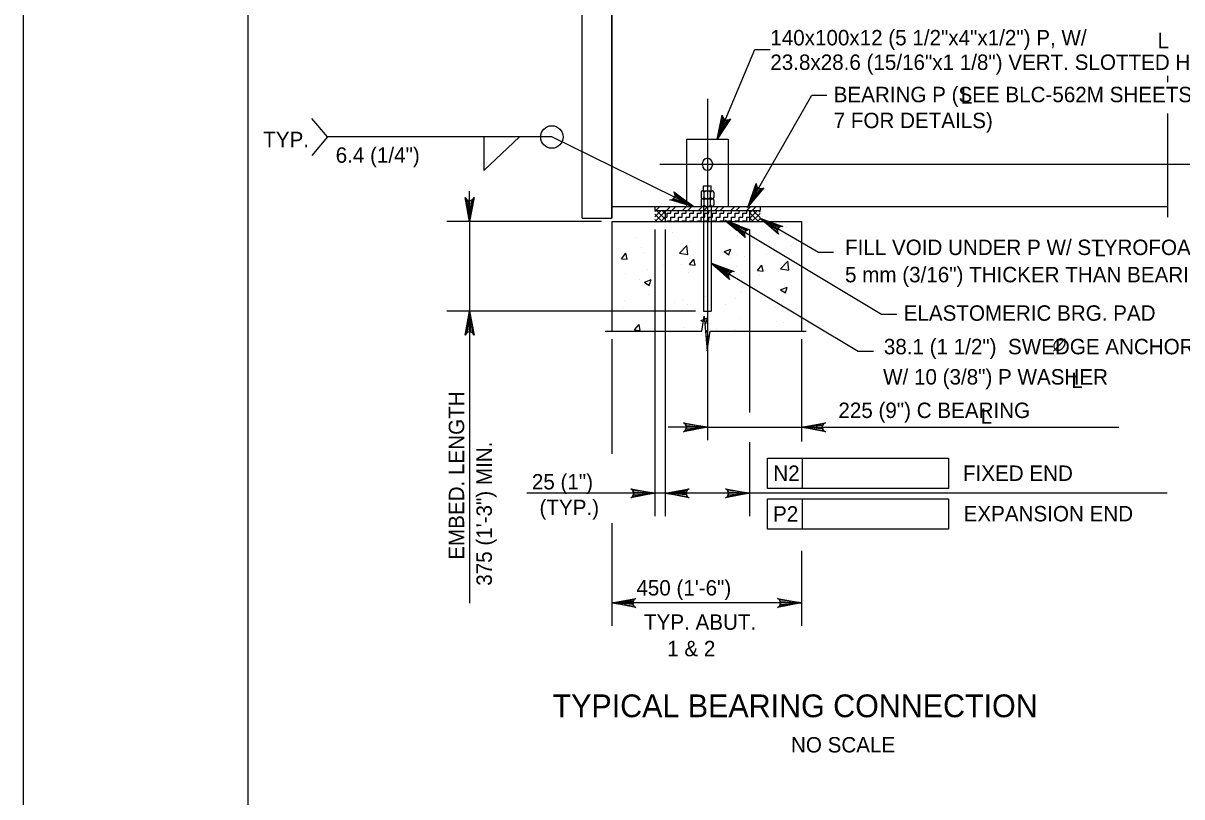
# Model space of a CAD drawing. Extents: x -13 to 81, y -176 to 0.
# Drawn here: x 34 to 43.02, y -9.75 to -3.73 of the extents above; entities that cross this region are included whole.
import ezdxf

# ---------------------------------------------------------------- set-up
doc = ezdxf.new("R2010")
doc.units = 0
for name, color, linetype in [('Level 1', 7, 'Continuous'), ('Level 3', 7, 'Continuous'), ('Level 4', 7, 'Continuous'), ('Level 5', 7, 'Continuous'), ('Level 63', 7, 'Continuous')]:
    doc.layers.add(name, color=color, linetype=linetype)

msp = doc.modelspace()

# ---------------------------------------------------------------- linework, layer by layer
at = {"layer": 'Level 1'}
msp.add_lwpolyline([(35.75, -21.25), (67.25, -21.25), (67.25, -0.75), (35.75, -0.75)], close=True, dxfattribs=at)
at = {"layer": 'Level 3'}
for p, q in [((39.4044, -4.6283), (39.6992, -3.9318)), ((39.6992, -3.9318), (39.8173, -3.9318)), ((39.3284, -4.3155), (39.3284, -6.9741)), ((39.6465, -5.1532), (40.1412, -4.2862)), ((40.1412, -4.2862), (40.2594, -4.2862)), ((36.3697, -4.6125), (36.2473, -4.4683)), ((36.3697, -4.6125), (36.2473, -4.7568)), ((38.118, -4.6125), (36.3697, -4.6125)), ((37.5872, -4.8722), (37.8663, -4.6125)), ((37.5872, -4.6125), (37.5872, -4.8722)), ((39.2193, -5.1531), (38.118, -4.6125)), ((38.9577, -4.8252), (43.8916, -4.8252)), ((37.4768, -5.2704), (37.4768, -5.0343)), ((38.5043, -5.2704), (37.2997, -5.2704)), ((37.4768, -5.2704), (37.4768, -5.9682)), ((39.4819, -5.2704), (40.6852, -5.9912)), ((39.756, -5.2555), (40.1938, -5.5085)), ((38.9183, -5.332), (38.9183, -7.5638)), ((39.0003, -5.332), (39.0003, -7.5638)), ((39.6565, -5.332), (39.6565, -6.7582)), ((40.1938, -5.5085), (40.3119, -5.5085)), ((39.3592, -5.5952), (40.5042, -6.2796)), ((39.2362, -5.9682), (37.2997, -5.9682)), ((37.4768, -5.9682), (37.4768, -8.2408)), ((40.6852, -5.9912), (40.8033, -5.9912)), ((38.5848, -6.1858), (38.5848, -7.0792)), ((40.0613, -6.1858), (40.0613, -6.9835)), ((40.5042, -6.2796), (40.6223, -6.2796)), ((40.0613, -6.7315), (40.0613, -6.9263)), ((39.1699, -6.8719), (39.0224, -6.8719)), ((39.288, -6.8719), (42.5324, -6.8719)), ((39.6565, -6.9891), (39.6565, -7.5638)), ((39.7956, -7.1132), (40.0694, -7.1132)), ((39.7956, -7.3495), (39.7956, -7.1132)), ((40.0694, -7.3495), (40.0694, -7.1132)), ((40.0694, -7.1132), (41.2076, -7.1132)), ((41.2076, -7.1132), (41.2076, -7.3495)), ((42.9101, -7.3867), (37.9217, -7.3867)), ((41.2076, -7.3495), (39.7956, -7.3495)), ((39.7956, -7.4286), (40.0694, -7.4286)), ((39.7956, -7.6647), (39.7956, -7.4286)), ((40.0694, -7.6647), (40.0694, -7.4286)), ((40.0694, -7.4286), (41.2076, -7.4286)), ((41.2076, -7.4286), (41.2076, -7.6647)), ((38.5848, -7.6193), (38.5848, -8.4177)), ((41.2076, -7.6647), (39.7956, -7.6647)), ((40.0613, -7.8337), (40.0613, -8.4177)), ((40.0613, -8.2406), (38.5848, -8.2406))]:
    msp.add_line(p, q, dxfattribs=at)
for points in [[(39.4044, -4.6283), (39.4449, -4.443), (39.4484, -4.4602), (39.4571, -4.4718), (39.4677, -4.4787), (39.4801, -4.4816), (39.4945, -4.4797), (39.5093, -4.4703), (39.4044, -4.6283), (39.4945, -4.4797), (39.4801, -4.4816), (39.4044, -4.6283), (39.4677, -4.4787), (39.4571, -4.4718), (39.4044, -4.6283), (39.4484, -4.4602)], [(39.2193, -5.1531), (39.0366, -5.1023), (39.0538, -5.0998), (39.066, -5.0918), (39.0735, -5.0815), (39.0771, -5.0693), (39.0759, -5.0548), (39.0674, -5.0396), (39.2193, -5.1531), (39.0759, -5.0548), (39.0771, -5.0693), (39.2193, -5.1531), (39.0735, -5.0815), (39.066, -5.0918), (39.2193, -5.1531), (39.0538, -5.0998)], [(39.6465, -5.1532), (39.7085, -4.974), (39.7101, -4.9914), (39.7172, -5.0041), (39.727, -5.0121), (39.7389, -5.0164), (39.7535, -5.0162), (39.7692, -5.0087), (39.6465, -5.1532), (39.7535, -5.0162), (39.7389, -5.0164), (39.6465, -5.1532), (39.727, -5.0121), (39.7172, -5.0041), (39.6465, -5.1532), (39.7101, -4.9914)], [(37.4768, -5.2704), (37.4419, -5.084), (37.4518, -5.0983), (37.4643, -5.1057), (37.4768, -5.1079), (37.4893, -5.1057), (37.5018, -5.0983), (37.5117, -5.084), (37.4768, -5.2704), (37.5018, -5.0983), (37.4893, -5.1057), (37.4768, -5.2704), (37.4768, -5.1079), (37.4643, -5.1057), (37.4768, -5.2704), (37.4518, -5.0983)], [(39.4819, -5.2704), (39.6598, -5.3362), (39.6423, -5.3374), (39.6296, -5.3443), (39.6213, -5.3539), (39.6167, -5.3658), (39.6167, -5.3803), (39.6239, -5.3962), (39.4819, -5.2704), (39.6167, -5.3803), (39.6167, -5.3658), (39.4819, -5.2704), (39.6213, -5.3539), (39.6296, -5.3443), (39.4819, -5.2704), (39.6423, -5.3374)], [(39.7376, -5.2451), (39.9165, -5.3081), (39.8991, -5.3095), (39.8864, -5.3166), (39.8783, -5.3263), (39.8739, -5.3382), (39.8741, -5.3528), (39.8815, -5.3686), (39.7376, -5.2451), (39.8741, -5.3528), (39.8739, -5.3382), (39.7376, -5.2451), (39.8783, -5.3263), (39.8864, -5.3166), (39.7376, -5.2451), (39.8991, -5.3095)], [(39.3592, -5.5952), (39.5371, -5.6608), (39.5197, -5.662), (39.5069, -5.6689), (39.4987, -5.6785), (39.4941, -5.6903), (39.494, -5.7049), (39.5012, -5.7208), (39.3592, -5.5952), (39.494, -5.7049), (39.4941, -5.6903), (39.3592, -5.5952), (39.4987, -5.6785), (39.5069, -5.6689), (39.3592, -5.5952), (39.5197, -5.662)], [(37.4768, -5.9682), (37.5117, -6.1546), (37.5018, -6.1402), (37.4893, -6.1328), (37.4768, -6.1307), (37.4643, -6.1328), (37.4518, -6.1402), (37.4419, -6.1546), (37.4768, -5.9682), (37.4518, -6.1402), (37.4643, -6.1328), (37.4768, -5.9682), (37.4768, -6.1307), (37.4893, -6.1328), (37.4768, -5.9682), (37.5018, -6.1402)], [(39.3284, -6.8719), (39.142, -6.9068), (39.1563, -6.8969), (39.1638, -6.8844), (39.1659, -6.8719), (39.1638, -6.8594), (39.1563, -6.8469), (39.142, -6.837), (39.3284, -6.8719), (39.1563, -6.8469), (39.1638, -6.8594), (39.3284, -6.8719), (39.1659, -6.8719), (39.1638, -6.8844), (39.3284, -6.8719), (39.1563, -6.8969)], [(40.0613, -6.8719), (40.2477, -6.837), (40.2334, -6.8469), (40.226, -6.8594), (40.2238, -6.8719), (40.226, -6.8844), (40.2334, -6.8969), (40.2477, -6.9068), (40.0613, -6.8719), (40.2334, -6.8969), (40.226, -6.8844), (40.0613, -6.8719), (40.2238, -6.8719), (40.226, -6.8594), (40.0613, -6.8719), (40.2334, -6.8469)], [(38.9183, -7.3867), (38.7318, -7.4216), (38.7462, -7.4117), (38.7536, -7.3992), (38.7557, -7.3867), (38.7536, -7.3742), (38.7462, -7.3617), (38.7318, -7.3518), (38.9183, -7.3867), (38.7462, -7.3617), (38.7536, -7.3742), (38.9183, -7.3867), (38.7557, -7.3867), (38.7536, -7.3992), (38.9183, -7.3867), (38.7462, -7.4117)], [(39.0003, -7.3867), (39.1867, -7.3518), (39.1724, -7.3617), (39.165, -7.3742), (39.1628, -7.3867), (39.165, -7.3992), (39.1724, -7.4117), (39.1867, -7.4216), (39.0003, -7.3867), (39.1724, -7.4117), (39.165, -7.3992), (39.0003, -7.3867), (39.1628, -7.3867), (39.165, -7.3742), (39.0003, -7.3867), (39.1724, -7.3617)], [(39.6565, -7.3867), (39.4701, -7.4216), (39.4844, -7.4117), (39.4918, -7.3992), (39.494, -7.3867), (39.4918, -7.3742), (39.4844, -7.3617), (39.4701, -7.3518), (39.6565, -7.3867), (39.4844, -7.3617), (39.4918, -7.3742), (39.6565, -7.3867), (39.494, -7.3867), (39.4918, -7.3992), (39.6565, -7.3867), (39.4844, -7.4117)], [(38.5848, -8.2406), (38.7713, -8.2057), (38.7569, -8.2156), (38.7495, -8.2281), (38.7473, -8.2406), (38.7495, -8.2531), (38.7569, -8.2656), (38.7713, -8.2755), (38.5848, -8.2406), (38.7569, -8.2656), (38.7495, -8.2531), (38.5848, -8.2406), (38.7473, -8.2406), (38.7495, -8.2281), (38.5848, -8.2406), (38.7569, -8.2156)], [(40.0613, -8.2406), (39.8749, -8.2755), (39.8892, -8.2656), (39.8967, -8.2531), (39.8988, -8.2406), (39.8967, -8.2281), (39.8892, -8.2156), (39.8749, -8.2057), (40.0613, -8.2406), (39.8892, -8.2156), (39.8967, -8.2281), (40.0613, -8.2406), (39.8988, -8.2406), (39.8967, -8.2531), (40.0613, -8.2406), (39.8892, -8.2656)]]:
    msp.add_lwpolyline(points, dxfattribs=at)
for points in [[(39.4686, -4.5272), (39.4323, -4.5119), (39.4044, -4.6283)], [(39.7157, -5.0716), (39.6816, -5.0521), (39.64, -5.1643)], [(39.1223, -5.0835), (39.1049, -5.1188), (39.2196, -5.1532)], [(37.4572, -5.1523), (37.4965, -5.1523), (37.4768, -5.2704)], [(39.5583, -5.339), (39.5784, -5.3053), (39.467, -5.2614)], [(39.4504, -5.6727), (39.4707, -5.6389), (39.3592, -5.5952)], [(37.4572, -6.0862), (37.4965, -6.0862), (37.4768, -5.9682)], [(40.1794, -6.8522), (40.1794, -6.8916), (40.0613, -6.8719)]]:
    msp.add_lwpolyline(points, close=True, dxfattribs=at)
msp.add_circle((38.118, -4.6125), 0.0875, dxfattribs=at)
at = {"layer": 'Level 4'}
msp.add_line((42.0244, -6.2812), (42.114, -6.1832), dxfattribs=at)
msp.add_spline([(42.1047, -6.1928), (42.0977, -6.1874), (42.0907, -6.1855), (42.082, -6.1848), (42.0768, -6.1848), (42.0683, -6.1867), (42.0603, -6.1903), (42.0549, -6.1934), (42.0443, -6.2019), (42.036, -6.2127), (42.031, -6.2227), (42.0281, -6.232), (42.0272, -6.2407), (42.0281, -6.248), (42.0317, -6.2586), (42.0356, -6.264), (42.0432, -6.2699), (42.0547, -6.2727), (42.068, -6.2722), (42.0847, -6.2646), (42.0969, -6.2542), (42.1061, -6.2414), (42.1121, -6.2282), (42.1141, -6.2135), (42.1115, -6.204), (42.1052, -6.1928)], degree=3, dxfattribs=at)
at = {"layer": 'Level 5'}
for p, q in [((38.3542, -5.2458), (38.3542, -2.1492)), ((38.5848, -5.2458), (38.5848, -2.1492)), ((38.5848, -2.4465), (38.5848, -5.2458)), ((42.9128, -4.137), (42.9128, -4.1847)), ((42.9128, -4.4287), (42.9128, -5.2372)), ((39.1653, -4.6283), (39.4916, -4.6283)), ((39.1653, -4.6283), (39.1653, -5.1532)), ((39.4916, -4.6283), (39.4916, -5.1532)), ((39.2893, -4.8173), (39.2893, -4.8331)), ((39.3674, -4.8173), (39.3674, -4.8331)), ((39.2793, -5.0411), (39.2793, -5.084)), ((39.2909, -5.0322), (39.3667, -5.0322)), ((39.2977, -5.0322), (39.2977, -4.9931)), ((39.2977, -4.9931), (39.3592, -4.9931)), ((39.3034, -5.084), (39.3034, -5.0411)), ((39.3534, -5.084), (39.3534, -5.0411)), ((39.3592, -5.0322), (39.3592, -4.9931)), ((39.3792, -5.0411), (39.3792, -5.084)), ((39.2793, -5.1016), (39.2793, -5.1444)), ((39.2909, -5.0927), (39.3667, -5.0927)), ((39.2909, -5.0928), (39.3667, -5.0928)), ((39.2977, -5.0927), (39.3592, -5.0927)), ((39.3034, -5.1444), (39.3034, -5.1016)), ((39.3534, -5.1444), (39.3534, -5.1016)), ((39.3792, -5.1016), (39.3792, -5.1444)), ((38.5848, -5.1532), (40.0613, -5.1532)), ((38.9183, -5.1532), (38.9183, -5.184)), ((38.9183, -5.184), (39.7385, -5.184)), ((38.9183, -5.2337), (38.968, -5.184)), ((38.9183, -5.192), (38.9262, -5.184)), ((38.9763, -5.2704), (38.9183, -5.2125)), ((38.9233, -5.2704), (39.0003, -5.1935)), ((38.9262, -5.184), (38.9571, -5.1532)), ((39.0003, -5.2527), (38.9316, -5.184)), ((39.0003, -5.211), (38.9733, -5.184)), ((39.0003, -5.184), (39.0003, -5.2704)), ((39.0097, -5.184), (39.0406, -5.1532)), ((39.0148, -5.2063), (39.0443, -5.2063)), ((39.0148, -5.2358), (39.0148, -5.2063)), ((39.0443, -5.2063), (39.0443, -5.184)), ((39.0515, -5.184), (39.0823, -5.1532)), ((39.0739, -5.2063), (39.1034, -5.2063)), ((39.0739, -5.2358), (39.0739, -5.2063)), ((39.1034, -5.2063), (39.1034, -5.184)), ((39.1329, -5.2063), (39.1625, -5.2063)), ((39.1329, -5.2358), (39.1329, -5.2063)), ((39.1351, -5.184), (39.1658, -5.1532)), ((39.1625, -5.2063), (39.1625, -5.184)), ((39.1768, -5.184), (39.2076, -5.1532)), ((39.192, -5.2063), (39.2215, -5.2063)), ((39.192, -5.2358), (39.192, -5.2063)), ((39.2215, -5.2063), (39.2215, -5.184)), ((39.2511, -5.2063), (39.2806, -5.2063)), ((39.2511, -5.2358), (39.2511, -5.2063)), ((39.2603, -5.184), (39.2912, -5.1532)), ((39.2806, -5.2063), (39.2806, -5.184)), ((39.2909, -5.1532), (39.3667, -5.1532)), ((39.2977, -5.1532), (39.3592, -5.1532)), ((39.2977, -5.1532), (39.2977, -5.9682)), ((39.3021, -5.184), (39.3329, -5.1532)), ((39.3101, -5.2063), (39.3284, -5.2063)), ((39.3101, -5.2358), (39.3101, -5.2063)), ((39.3284, -5.2063), (39.3397, -5.2063)), ((39.3397, -5.2063), (39.3397, -5.184)), ((39.3592, -5.1532), (39.3592, -5.9682)), ((39.3692, -5.2063), (39.3987, -5.2063)), ((39.3692, -5.2358), (39.3692, -5.2063)), ((39.3856, -5.184), (39.4164, -5.1532)), ((39.3987, -5.2063), (39.3987, -5.184)), ((39.4273, -5.184), (39.4582, -5.1532)), ((39.4282, -5.2063), (39.4577, -5.2063)), ((39.4282, -5.2358), (39.4282, -5.2063)), ((39.4577, -5.2063), (39.4577, -5.184)), ((39.4872, -5.2063), (39.5168, -5.2063)), ((39.4872, -5.2358), (39.4872, -5.2063)), ((39.5108, -5.184), (39.5417, -5.1532)), ((39.5168, -5.2063), (39.5168, -5.184)), ((39.5463, -5.2063), (39.5758, -5.2063)), ((39.5463, -5.2358), (39.5463, -5.2063)), ((39.5527, -5.184), (39.5834, -5.1532)), ((39.5758, -5.2063), (39.5758, -5.184)), ((39.6054, -5.2063), (39.6349, -5.2063)), ((39.6054, -5.2358), (39.6054, -5.2063)), ((39.6349, -5.2063), (39.6349, -5.184)), ((39.6362, -5.184), (39.6669, -5.1532)), ((39.6565, -5.184), (39.6565, -5.2704)), ((39.6565, -5.2054), (39.6779, -5.184)), ((39.6565, -5.2472), (39.7197, -5.184)), ((39.7279, -5.2704), (39.6565, -5.1991)), ((39.675, -5.2704), (39.7385, -5.2069)), ((39.6779, -5.184), (39.7088, -5.1532)), ((39.7385, -5.2393), (39.6833, -5.184)), ((39.7385, -5.1976), (39.725, -5.184)), ((39.7385, -5.1532), (39.7385, -5.184)), ((40.0613, -5.1532), (42.9128, -5.1532)), ((38.3542, -5.2458), (38.5848, -5.2458)), ((38.5848, -5.2704), (40.0613, -5.2704)), ((38.5848, -5.2704), (38.5848, -6.1243)), ((38.9345, -5.2704), (38.9183, -5.2542)), ((38.9651, -5.2704), (39.0003, -5.2352)), ((39.0003, -5.2358), (39.0148, -5.2358)), ((39.0148, -5.2653), (39.0443, -5.2653)), ((39.0148, -5.2704), (39.0148, -5.2653)), ((39.0443, -5.2358), (39.0739, -5.2358)), ((39.0443, -5.2653), (39.0443, -5.2358)), ((39.0739, -5.2653), (39.1034, -5.2653)), ((39.0739, -5.2704), (39.0739, -5.2653)), ((39.1034, -5.2358), (39.1329, -5.2358)), ((39.1034, -5.2653), (39.1034, -5.2358)), ((39.1329, -5.2653), (39.1625, -5.2653)), ((39.1329, -5.2704), (39.1329, -5.2653)), ((39.1625, -5.2358), (39.192, -5.2358)), ((39.1625, -5.2653), (39.1625, -5.2358)), ((39.192, -5.2653), (39.2215, -5.2653)), ((39.192, -5.2704), (39.192, -5.2653)), ((39.2215, -5.2358), (39.2511, -5.2358)), ((39.2215, -5.2653), (39.2215, -5.2358)), ((39.2511, -5.2653), (39.2806, -5.2653)), ((39.2511, -5.2704), (39.2511, -5.2653)), ((39.2806, -5.2358), (39.2977, -5.2358)), ((39.2806, -5.2653), (39.2806, -5.2358)), ((39.2977, -5.2358), (39.3101, -5.2358)), ((39.3101, -5.2653), (39.3284, -5.2653)), ((39.3101, -5.2704), (39.3101, -5.2653)), ((39.3284, -5.2653), (39.3397, -5.2653)), ((39.3397, -5.2358), (39.3592, -5.2358)), ((39.3397, -5.2653), (39.3397, -5.2358)), ((39.3592, -5.2358), (39.3692, -5.2358)), ((39.3692, -5.2653), (39.3987, -5.2653)), ((39.3692, -5.2704), (39.3692, -5.2653)), ((39.3987, -5.2358), (39.4282, -5.2358)), ((39.3987, -5.2653), (39.3987, -5.2358)), ((39.4282, -5.2653), (39.4577, -5.2653)), ((39.4282, -5.2704), (39.4282, -5.2653)), ((39.4577, -5.2358), (39.4872, -5.2358)), ((39.4577, -5.2653), (39.4577, -5.2358)), ((39.4872, -5.2653), (39.5168, -5.2653)), ((39.4872, -5.2704), (39.4872, -5.2653)), ((39.5168, -5.2358), (39.5463, -5.2358)), ((39.5168, -5.2653), (39.5168, -5.2358)), ((39.5207, -5.2949), (39.5207, -5.2949)), ((39.5463, -5.2653), (39.5758, -5.2653)), ((39.5463, -5.2704), (39.5463, -5.2653)), ((39.5758, -5.2358), (39.6054, -5.2358)), ((39.5758, -5.2653), (39.5758, -5.2358)), ((39.6054, -5.2653), (39.6349, -5.2653)), ((39.6054, -5.2704), (39.6054, -5.2653)), ((39.6349, -5.2358), (39.6565, -5.2358)), ((39.6349, -5.2653), (39.6349, -5.2358)), ((39.6862, -5.2704), (39.6565, -5.2408)), ((39.7054, -5.2706), (39.7054, -5.2706)), ((39.7167, -5.2704), (39.7385, -5.2487)), ((39.9479, -5.3204), (39.9479, -5.3204)), ((40.0613, -5.2704), (40.0613, -6.1243)), ((38.7748, -5.3932), (38.7748, -5.3932)), ((39.0544, -5.3563), (39.0544, -5.3563)), ((39.5646, -5.3758), (39.5646, -5.3758)), ((38.5901, -5.4175), (38.5901, -5.4175)), ((38.8127, -5.475), (38.8127, -5.475)), ((39.1103, -5.5177), (39.1677, -5.4577)), ((39.1759, -5.5279), (39.1677, -5.4577)), ((39.1917, -5.4231), (39.1917, -5.4231)), ((39.4585, -5.5051), (39.5102, -5.4852)), ((39.4952, -5.5298), (39.5102, -5.4852)), ((39.9859, -5.4552), (39.9859, -5.4552)), ((38.589, -5.5938), (38.589, -5.5938)), ((38.6589, -5.56), (38.6946, -5.5176)), ((38.6589, -5.56), (38.7031, -5.5638)), ((38.7031, -5.5638), (38.6946, -5.5176)), ((38.8274, -5.5112), (38.8274, -5.5112)), ((39.1103, -5.5177), (39.1759, -5.5278)), ((39.1884, -5.6063), (39.224, -5.5639)), ((39.2214, -5.5279), (39.2214, -5.5279)), ((39.2326, -5.6102), (39.224, -5.5639)), ((39.3265, -5.5861), (39.3265, -5.5861)), ((39.4585, -5.5051), (39.4952, -5.5298)), ((39.5112, -5.5617), (39.5112, -5.5617)), ((39.5554, -5.5292), (39.5554, -5.5292)), ((39.6155, -5.5446), (39.6155, -5.5446)), ((39.7908, -5.5249), (39.7908, -5.5249)), ((39.8981, -5.6398), (39.9556, -5.5799)), ((39.939, -5.5662), (39.939, -5.5662)), ((39.9637, -5.6501), (39.9556, -5.5799)), ((40.0096, -5.5613), (40.0096, -5.5613)), ((38.6944, -5.6769), (38.6944, -5.6769)), ((38.8603, -5.6475), (38.8603, -5.6475)), ((38.9831, -5.6104), (38.9831, -5.6104)), ((39.1249, -5.603), (39.1249, -5.603)), ((39.1827, -5.6688), (39.1827, -5.6688)), ((39.1884, -5.6063), (39.2326, -5.6102)), ((39.3771, -5.6271), (39.3771, -5.6271)), ((39.5556, -5.6215), (39.5556, -5.6215)), ((39.7179, -5.6527), (39.7535, -5.6102)), ((39.7179, -5.6527), (39.762, -5.6565)), ((39.762, -5.6565), (39.7535, -5.6102)), ((39.7712, -5.6437), (39.7712, -5.6437)), ((39.8981, -5.6398), (39.9637, -5.6501)), ((38.8038, -5.7207), (38.8038, -5.7207)), ((38.8383, -5.7432), (38.89, -5.7233)), ((38.8383, -5.7432), (38.875, -5.7679)), ((38.875, -5.7679), (38.89, -5.7233)), ((39.3017, -5.7651), (39.3017, -5.7651)), ((39.7323, -5.6913), (39.7323, -5.6913)), ((38.8713, -5.839), (38.8713, -5.839)), ((39.3171, -5.8529), (39.3171, -5.8529)), ((39.5967, -5.8161), (39.5967, -5.8161)), ((39.8992, -5.8022), (39.9508, -5.7824)), ((39.8992, -5.8022), (39.9359, -5.827)), ((39.93, -5.8119), (39.93, -5.8119)), ((39.9359, -5.827), (39.9508, -5.7824)), ((38.6661, -5.9387), (38.6661, -5.9387)), ((38.6805, -5.8865), (38.6805, -5.8865)), ((39.0746, -5.9032), (39.0746, -5.9032)), ((39.1322, -5.8773), (39.1322, -5.8773)), ((39.1737, -5.9145), (39.1737, -5.9145)), ((39.4687, -5.9198), (39.4687, -5.9198)), ((39.5466, -5.8672), (39.5466, -5.8672)), ((39.8627, -5.9365), (39.8627, -5.9365)), ((40.0142, -5.9496), (40.0142, -5.9496)), ((38.7948, -5.9665), (38.7948, -5.9665)), ((39.2789, -6.0403), (39.2989, -6.0327)), ((39.2789, -6.0403), (39.2959, -6.0518)), ((39.2845, -6.1243), (39.3027, -6.0083)), ((39.2977, -5.9682), (39.3592, -5.9682)), ((39.3027, -6.0083), (39.3263, -6.2787)), ((39.3047, -6.0305), (39.3306, -6.0205)), ((39.3157, -6.0652), (39.3306, -6.0205)), ((39.5838, -6.0234), (39.5838, -6.0234)), ((40.0534, -6.0216), (40.0534, -6.0216)), ((38.5322, -6.1243), (39.2845, -6.1243)), ((38.7614, -6.1152), (38.797, -6.0728)), ((38.7614, -6.1152), (38.8055, -6.1191)), ((38.8055, -6.1192), (38.797, -6.0728)), ((39.1532, -6.0973), (39.1532, -6.0973)), ((39.3072, -6.0594), (39.3157, -6.0651)), ((39.3137, -6.1343), (39.3264, -6.1192)), ((39.3263, -6.2787), (39.3509, -6.1243)), ((39.335, -6.1654), (39.3264, -6.1192)), ((39.3509, -6.1243), (40.0969, -6.1243)), ((39.4024, -6.1072), (39.4024, -6.1072)), ((39.5376, -6.113), (39.5376, -6.113)), ((39.8687, -6.0459), (39.8687, -6.0459)), ((39.921, -6.0577), (39.921, -6.0577)), ((39.3163, -6.1638), (39.335, -6.1654))]:
    msp.add_line(p, q, dxfattribs=at)
for centre, radius, start, end in [((39.3284, -4.8172), 0.039, 0, 180), ((39.3284, -4.833), 0.039, 180, 0), ((39.2914, -5.0449), 0.0126, 17.45181, 162.54819), ((39.3284, -5.072), 0.0398, 51.05, 128.95), ((39.3664, -5.0461), 0.0139, 91.82706, 158.71306), ((39.3664, -5.0461), 0.0139, 21.28694, 91.82706), ((39.2914, -5.0802), 0.0126, 197.45181, 342.54819), ((39.2914, -5.1053), 0.0126, 17.45181, 162.54819), ((39.3284, -5.053), 0.0398, 231.05, 308.95), ((39.3284, -5.1325), 0.0398, 51.05, 128.95), ((39.3664, -5.0789), 0.0139, 201.28694, 268.17294), ((39.3664, -5.1066), 0.0139, 91.82706, 158.71306), ((39.3664, -5.0789), 0.0139, 268.17294, 338.71305), ((39.3664, -5.1066), 0.0139, 21.28694, 91.82706), ((39.2914, -5.1406), 0.0126, 197.45181, 342.54819), ((39.3284, -5.1135), 0.0398, 231.05, 308.95), ((39.3664, -5.1394), 0.0139, 201.28694, 268.17294), ((39.3664, -5.1394), 0.0139, 268.17294, 338.71305)]:
    msp.add_arc(centre, radius, start, end, dxfattribs=at)
at = {"layer": 'Level 63'}
msp.add_lwpolyline([(34, -22), (68, -22), (68, 0), (34, 0)], close=True, dxfattribs=at)

# ---------------------------------------------------------------- texts
at = {"layer": 'Level 3'}
for s, height, p in [('BEARING P (SEE BLC-562M SHEETS 5, 6, & ', 0.12, (40.3123, -4.3418)), ('L', 0.12, (41.3023, -4.354)), ('7 FOR DETAILS)', 0.12, (40.3123, -4.5436)), ('TYP.', 0.12, (35.8696, -4.692)), ('FILL VOID UNDER P W/ STYROFOAM,', 0.12, (40.4006, -5.5315)), ('L', 0.12, (42.342, -5.5415)), ('5 mm (3/16") THICKER THAN BEARING PAD', 0.12, (40.4006, -5.7439)), ('ELASTOMERIC BRG. PAD', 0.12, (40.8574, -6.0432)), ('38.1 (1 1/2")  SWEDGE ANCHOR BOLT', 0.12, (40.703, -6.3045)), ('W/ 10 (3/8") P WASHER', 0.12, (40.6972, -6.5399)), ('L', 0.12, (42.1635, -6.5671)), ('225 (9") C BEARING', 0.12, (40.349, -6.8006)), ('L', 0.12, (41.4567, -6.8452)), ('N2', 0.12, (39.8421, -7.2901)), ('FIXED END', 0.12, (41.3192, -7.2901)), ('25 (1")', 0.12, (37.9618, -7.3568)), ('(TYP.)', 0.12, (38.0213, -7.5568)), ('P2', 0.12, (39.8401, -7.6069)), ('EXPANSION END', 0.12, (41.3243, -7.6054)), ('450 (1\'-6")', 0.12, (38.7758, -8.1825)), ('TYP. ABUT.', 0.12, (38.835, -8.4492)), ('1 & 2', 0.12, (39.0159, -8.6553)), ('TYPICAL BEARING CONNECTION', 0.177167, (38.1229, -9.1299)), ('NO SCALE', 0.12, (39.9799, -9.4045))]:
    msp.add_text(s, height=height, dxfattribs=at).set_placement(p)
for s, p in [('EMBED. LENGTH', (37.4345, -7.9039)), ('375 (1\'-3") MIN.', (37.6502, -8.1063))]:
    msp.add_text(s, height=0.12, rotation=90, dxfattribs=at).set_placement(p)
at = {"layer": 'Level 4'}
for s, p in [('140x100x12 (5 1/2"x4"x1/2") P, W/', (39.8188, -3.8992)), ('L', (42.8342, -3.9214)), ('23.8x28.6 (15/16"x1 1/8") VERT. SLOTTED HOLE', (39.8188, -4.0904)), ('6.4 (1/4")', (36.434, -4.8133))]:
    msp.add_text(s, height=0.12, dxfattribs=at).set_placement(p)

doc.saveas('drawing.dxf')
